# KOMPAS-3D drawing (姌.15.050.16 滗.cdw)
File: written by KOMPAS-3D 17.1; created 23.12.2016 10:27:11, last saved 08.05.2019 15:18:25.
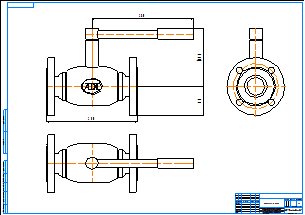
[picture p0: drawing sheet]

Sheet 1: A1, landscape

Title block, sheet 1: name: КШ.15.050.16 фф; material: Внимание! Данный продукт является объектом авторского права ООО «Торговый Дом АДЛ». / Запрещается изменение, копирование, распространение / (в том числе путем копирования на другие сайты и ресурсы в Интернете) / или любое иное использование информации и объектов без предварительного / согласия правообладателя (ООО «Торговый Дом АДЛ»).; sheets: 1; organisation: ООО "Торговый дом АДЛ"; sheet format: A1; stored path: C:\Users\tra\Desktop\2д чертежи\Шаровые краны БИВАЛ\КШ_Бивал_серия_14_15\KOMPAS_2D\КШ.15.050.16 фф.cdw

Views: Вид 1, Проекционный вид 2, Проекционный вид 3
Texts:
  Klimkovich
  ADL
Dimensions and other numbers on the sheet: 250; 280; 159,3; 80; 1:1; 1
